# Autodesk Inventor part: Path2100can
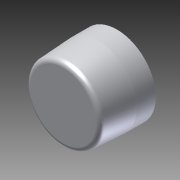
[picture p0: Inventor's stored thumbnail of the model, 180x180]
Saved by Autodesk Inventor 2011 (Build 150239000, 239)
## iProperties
Created: 2014-07
Part Number: Path2100can
Document SubType Name: Modeling
Designer: Evgeny
Density: 1 g/cm^3
Author: Evgeny
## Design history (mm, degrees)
sketch "Эскиз2"
  geometry: L1 (0, -8.9)-(49, -8.9); L2 (49, -8.9)-(49, 15.1); L3 (49, 15.1)-(46.822, 53.44); L4 (40.831, 59.1)-(0, 59.1); L5 (0, 59.1)-(0, -8.9); A1 r 6 centre (40.831, 53.1) between (46.822, 53.44) and (40.831, 59.1); 2 further points
  constraints: 10 end point, 2 parallel, 2 point on circle, 2 point on line, 2 tangent, 1 centre point, 1 horizontal, 1 perpendicular
  dimensions: "d0" = 49 distance between parallel lines of L2 L5; "d1" = 68 distance of L4.end L1.start; "d2" = 46.5 distance from line of point (46.5, 59.1) L5; "d3" = 24 distance from line of L2.end L1; "d4" = 6 radius of A1; "d7" = 8.9 distance from line of L1 point (0, 0)
revolve "Вращение1" sketch "Эскиз2" stored, may be unused: angle "d5" = 90 deg
feature "Оболочка1" dims "d6" = 1
node "Твердое тело1"
